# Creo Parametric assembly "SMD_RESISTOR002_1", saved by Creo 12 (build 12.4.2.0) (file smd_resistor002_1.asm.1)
Units: Custom; MM, KILOGRAM, SECS

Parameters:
  PTC_WM_ITERATION = "0"
  PTC_WM_VERSION = "-.0"
  PTC_WM_LIFECYCLE_STATE = "In Work"
  PTC_WM_LIFECYCLE = "MO_CADDocument"
  PTC_WM_CREATED_BY = "Maximilian Roepper (Z0017RMS: MO)"
  PTC_WM_CREATED_ON = "18-Sep-26 11:36:42 AM"
  PTC_WM_MODIFIED_BY = "Maximilian Roepper (Z0017RMS: MO)"
  PTC_WM_MODIFIED_ON = "18-Sep-26 11:36:46 AM"
  PDMLINKNUMBER = "PDM000071454924"
  PTC_WM_NUMBER = "PDM000071454924"

Other parameters: WEIGHT, WEIGHT_FACTOR, WEIGHT_ADD, MC_ERRORS, SUPPLIER

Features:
  1. coordinate system
  2. imported feature
  3. component "BODY003_1"
  4. component "CONTACT016_1"
  5. component "CONTACT017_1"
  6. component "LABEL001_1"
  7. component "PART013_1"

Other named items: DRW_VIEW_ORG, ROUGH-GROB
